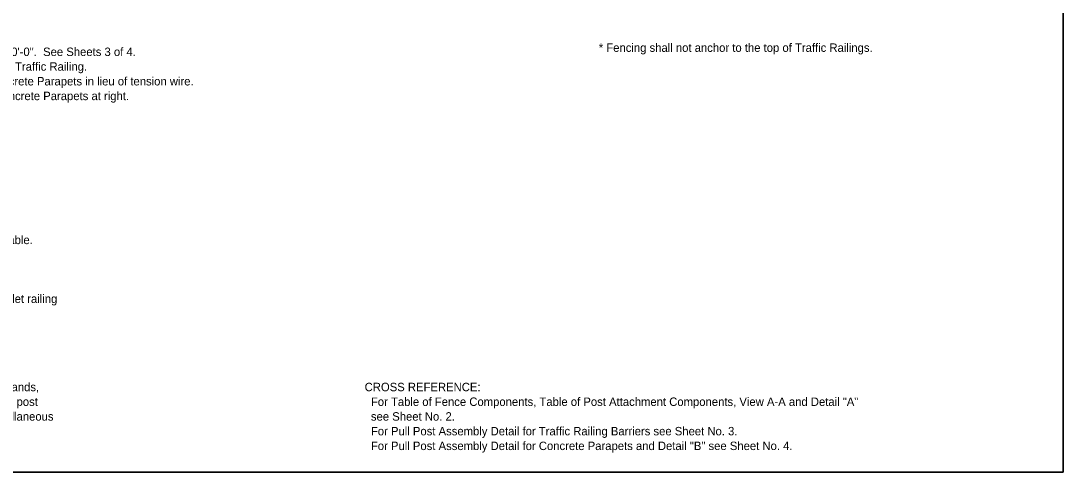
# Model space of a CAD drawing. Extents: x 0 to 41.1, y 0 to 25.9.
# Drawn here: x 16.13 to 41.05, y 0 to 10.8 of the extents above; entities that cross this region are included whole.
import ezdxf

# ---------------------------------------------------------------- set-up
doc = ezdxf.new("R2010")
doc.units = 0
for name, color, linetype in [('ActivePts-ConstElements', 7, 'Continuous'), ('Dimension', 7, 'Continuous'), ('Miscellaneous1', 7, 'Continuous')]:
    doc.layers.add(name, color=color, linetype=linetype)

msp = doc.modelspace()

# ---------------------------------------------------------------- linework, layer by layer
at = {"layer": 'ActivePts-ConstElements'}
msp.add_lwpolyline([(0, 0), (41.051, 0), (41.051, 25.946), (0, 25.946)], close=True, dxfattribs=at)
msp.add_lwpolyline([(0, 0), (41.051, 0), (41.051, 25.946), (0, 25.946)], close=True, dxfattribs=at)
msp.add_lwpolyline([(0, 0), (41.051, 0), (41.051, 25.946), (0, 25.946)], close=True, dxfattribs=at)
at = {"layer": 'Miscellaneous1'}
msp.add_lwpolyline([(0, 25.946), (41.051, 25.946), (41.051, 0), (0, 0)], close=True, dxfattribs=at)

# ---------------------------------------------------------------- texts
at = {"layer": 'Dimension'}
for s, p in [('* Fencing shall not anchor to the top of Traffic Railings.', (29.947, 10.057)), ('  1.   A Pull Post Assembly is required at maximum intervals of 500\'-0".  See Sheets 3 of 4.', (8.106, 9.958)), ('  2.  Brace rails are only required for vertical fence installations on Traffic Railing.  ', (8.106, 9.606)), ('  3.  Provide horizontal rails for vertical fence installations on Concrete Parapets in lieu of tension wire.  ', (8.106, 9.254)), ('      Locate horizontal rails as shown in the Typical Section for Concrete Parapets at right.', (8.106, 8.902)), ('CROSS REFERENCE:', (24.348, 1.937)), ('  For Table of Fence Components, Table of Post Attachment Components, View A-A and Detail "A"', (24.348, 1.585)), ('  see Sheet No. 2.', (24.348, 1.233)), ('  For Pull Post Assembly Detail for Traffic Railing Barriers see Sheet No. 3.', (24.348, 0.881)), ('  For Pull Post Assembly Detail for Concrete Parapets and Detail "B" see Sheet No. 4.', (24.348, 0.529))]:
    msp.add_text(s, height=0.2016, dxfattribs=at).set_placement(p)
for s, p in [('  thickness of shim plates will be determined in the field.  Install chain link fence in accordance with ASTM F 567 as applicable.', (1.369, 5.457)), ('  See Index No. 521-820 - Pedestrian/Bicycle Railing for Concrete Parapet details.  Provide fencing in lieu of aluminum bullet railing ', (1.369, 4.049)), ('  Payment will be made under Fencing, Type R.  Payment includes posts, horizontal and expansion rails, brace rails and bands,', (1.369, 1.937)), ('  rail ends, combination rail ends, boulevard clamps, chain link fabric, tension wire, ties, hog rings, tension bars and bands, post', (1.369, 1.585)), ('  and loop caps, pipe clamps, base plates, anchor rods, bolts, nuts, washers, shim plates, spacers,  neoprene pads, miscellaneous', (1.369, 1.233))]:
    msp.add_text(s, height=0.2016, rotation=0, dxfattribs=at).set_placement(p)

doc.saveas('drawing.dxf')
